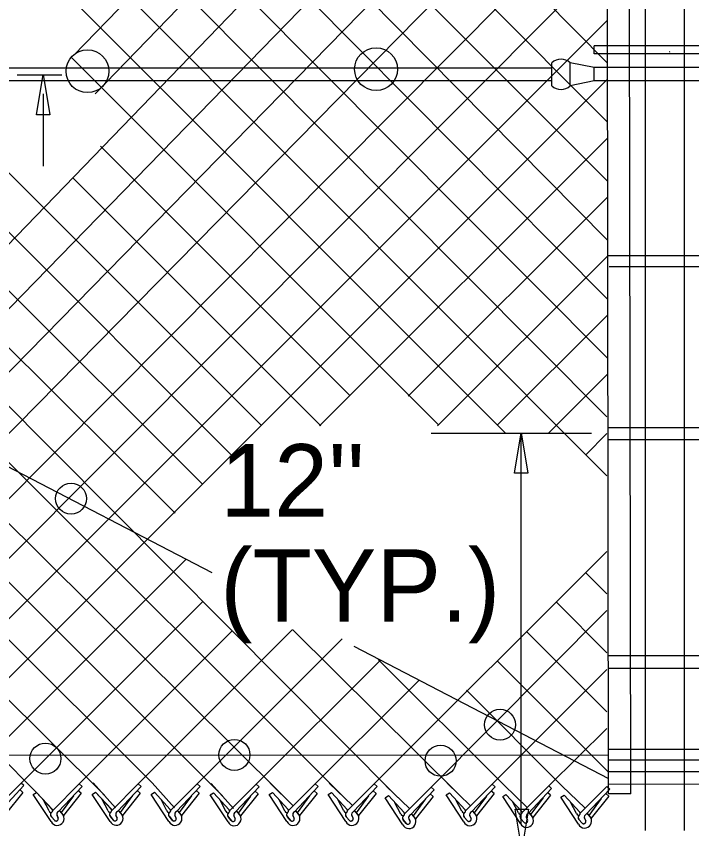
# Model space of a CAD drawing. Extents: x 0 to 1270, y 0 to 830.
# Drawn here: x 1076.4 to 1122.5, y 379.2 to 434.7 of the extents above; entities that cross this region are included whole.
import ezdxf

# ---------------------------------------------------------------- set-up
doc = ezdxf.new("R2010")
doc.units = 0
for name, color, linetype in [('CT_Dimensions', 7, 'Continuous'), ('sb_Chainlink Fence', 7, 'Continuous'), ('sb_Existing Structural Steel', 7, 'Continuous')]:
    doc.layers.add(name, color=color, linetype=linetype)

msp = doc.modelspace()

# ---------------------------------------------------------------- linework, layer by layer
at = {"layer": 'CT_Dimensions'}
for p, q in [((1076.416, 430.664), (1079.472, 430.664)), ((1078.212, 424.432), (1078.212, 429.374)), ((1104.699, 406.174), (1115.654, 406.174)), ((1110.838, 379.484), (1110.838, 406.15))]:
    msp.add_line(p, q, dxfattribs=at)
for points in [[(1077.742, 427.941), (1078.2, 430.69), (1078.658, 427.941)], [(1110.377, 403.447), (1110.835, 406.195), (1111.293, 403.447)], [(1111.347, 380.501), (1110.889, 377.753), (1110.431, 380.501)]]:
    msp.add_lwpolyline(points, close=True, dxfattribs=at)
at = {"layer": 'sb_Chainlink Fence'}
for p, q in [((1044.256, 382.248), (1098.445, 437.888)), ((1048.287, 382.219), (1102.547, 437.615)), ((1052.315, 382.241), (1106.711, 437.544)), ((1056.544, 382.282), (1111.127, 437.209)), ((1060.571, 382.293), (1115.159, 437.067)), ((1039.188, 436.446), (1094.487, 381.494)), ((1040.228, 382.257), (1093.004, 436.872)), ((1080.257, 431.977), (1084.95, 436.832)), ((1081.744, 429.361), (1088.977, 436.843)), ((1099.959, 436.36), (1116.708, 419.39)), ((1031.622, 436.195), (1085.642, 382.286)), ((1035.648, 436.213), (1090.432, 381.402)), ((1043.689, 436.242), (1098.531, 381.514)), ((1047.716, 436.271), (1102.424, 381.3)), ((1051.55, 436.141), (1087.218, 400.727)), ((1055.579, 436.14), (1089.078, 402.691)), ((1059.605, 436.158), (1091.036, 404.701)), ((1063.644, 436.155), (1093.051, 406.762)), ((1079.757, 436.244), (1109.778, 406.178)), ((1083.784, 436.262), (1116.704, 403.272)), ((1087.874, 436.269), (1116.705, 407.302)), ((1091.901, 436.28), (1116.706, 411.331)), ((1095.928, 436.309), (1116.707, 415.361)), ((1104.049, 436.097), (1116.709, 423.42)), ((1108.081, 436.119), (1116.71, 427.449)), ((1112.174, 436.119), (1116.711, 431.479)), ((1027.943, 435.607), (1082.374, 381.44)), ((1064.598, 382.284), (1116.712, 434.383)), ((1026.037, 433.482), (1077.739, 381.642)), ((1080.095, 431.873), (1105.213, 406.719)), ((1068.629, 382.255), (1116.711, 430.352)), ((1082.104, 425.788), (1099.132, 408.756)), ((1097.06, 406.674), (1116.71, 426.32)), ((1080.232, 423.61), (1097.161, 406.686)), ((1103.132, 408.718), (1116.709, 422.289)), ((1105.124, 406.677), (1116.708, 418.257)), ((1109.253, 406.777), (1116.707, 414.226)), ((1112.679, 406.17), (1116.706, 410.194)), ((1100.8, 382.218), (1116.703, 398.1)), ((1072.658, 382.277), (1087.952, 397.568)), ((1076.684, 382.28), (1089.074, 394.665)), ((1113.254, 394.631), (1116.701, 391.184)), ((1104.693, 382.004), (1116.702, 394.068)), ((1080.66, 382.22), (1091.09, 392.647)), ((1084.687, 382.231), (1095.231, 392.766)), ((1095.249, 392.753), (1106.591, 381.491)), ((1111.215, 392.637), (1116.7, 387.154)), ((1087.807, 381.312), (1098.624, 392.122)), ((1092.745, 382.192), (1101.229, 390.68)), ((1101.075, 390.712), (1109.653, 382.147)), ((1109.2, 390.621), (1116.811, 383.031)), ((1108.86, 382.195), (1116.701, 390.037)), ((1095.867, 381.304), (1103.895, 389.329)), ((1107.101, 388.623), (1113.619, 382.099)), ((1112.725, 382.083), (1116.7, 386.005)), ((1074.87, 380.458), (1076.684, 382.28)), ((1075.269, 380.387), (1076.882, 382.1)), ((1076.882, 382.1), (1076.684, 382.28)), ((1078.847, 380.399), (1080.66, 382.22)), ((1079.246, 380.328), (1080.858, 382.041)), ((1080.858, 382.041), (1080.66, 382.22)), ((1081.615, 382.294), (1083.133, 380.585)), ((1082.873, 380.409), (1084.687, 382.231)), ((1083.272, 380.338), (1084.885, 382.051)), ((1084.885, 382.051), (1084.687, 382.231)), ((1085.642, 382.286), (1087.16, 380.577)), ((1086.901, 380.401), (1088.714, 382.222)), ((1087.299, 380.33), (1088.912, 382.043)), ((1088.912, 382.043), (1088.714, 382.222)), ((1089.673, 382.256), (1091.191, 380.547)), ((1090.932, 380.371), (1092.745, 382.192)), ((1091.331, 380.3), (1092.943, 382.013)), ((1092.943, 382.013), (1092.745, 382.192)), ((1093.702, 382.278), (1095.273, 380.71)), ((1094.96, 380.393), (1096.774, 382.215)), ((1095.359, 380.322), (1096.972, 382.035)), ((1096.972, 382.035), (1096.774, 382.215)), ((1097.728, 382.281), (1099.333, 380.746)), ((1098.987, 380.396), (1100.8, 382.218)), ((1099.385, 380.325), (1100.998, 382.038)), ((1100.998, 382.038), (1100.8, 382.218)), ((1101.621, 382.068), (1103.226, 380.533)), ((1102.879, 380.183), (1104.693, 382.004)), ((1104.891, 381.825), (1104.693, 382.004)), ((1105.788, 382.259), (1107.393, 380.724)), ((1107.046, 380.374), (1108.86, 382.195)), ((1107.445, 380.303), (1109.058, 382.016)), ((1109.058, 382.016), (1108.86, 382.195)), ((1109.653, 382.147), (1111.258, 380.612)), ((1110.911, 380.262), (1112.725, 382.083)), ((1112.923, 381.904), (1112.725, 382.083)), ((1113.619, 382.099), (1115.224, 380.564)), ((1114.878, 380.214), (1116.691, 382.035)), ((1116.889, 381.856), (1116.691, 382.035)), ((1076.815, 381.637), (1075.608, 380.12)), ((1076.815, 381.637), (1076.617, 381.817)), ((1077.516, 381.49), (1077.739, 381.642)), ((1078.735, 379.646), (1077.516, 381.49)), ((1077.739, 381.642), (1078.817, 380.481)), ((1077.739, 381.642), (1078.824, 380.474)), ((1080.272, 381.412), (1079.423, 380.257)), ((1080.791, 381.578), (1079.585, 380.061)), ((1080.791, 381.578), (1080.593, 381.757)), ((1081.543, 381.5), (1081.766, 381.653)), ((1082.761, 379.656), (1081.543, 381.5)), ((1081.766, 381.653), (1082.844, 380.491)), ((1081.766, 381.653), (1082.851, 380.484)), ((1084.298, 381.422), (1083.45, 380.267)), ((1084.818, 381.588), (1083.611, 380.071)), ((1084.818, 381.588), (1084.62, 381.768)), ((1085.57, 381.492), (1085.793, 381.644)), ((1086.788, 379.647), (1085.57, 381.492)), ((1085.793, 381.644), (1086.871, 380.482)), ((1085.793, 381.644), (1086.878, 380.476)), ((1088.325, 381.414), (1087.477, 380.259)), ((1088.845, 381.58), (1087.639, 380.063)), ((1088.845, 381.58), (1088.647, 381.759)), ((1089.601, 381.462), (1089.824, 381.615)), ((1090.82, 379.618), (1089.601, 381.462)), ((1089.824, 381.615), (1090.902, 380.453)), ((1089.824, 381.615), (1090.909, 380.446)), ((1092.357, 381.384), (1091.508, 380.229)), ((1092.876, 381.55), (1091.67, 380.033)), ((1092.876, 381.55), (1092.678, 381.729)), ((1093.63, 381.485), (1093.853, 381.637)), ((1094.848, 379.64), (1093.63, 381.485)), ((1093.853, 381.637), (1094.931, 380.475)), ((1093.853, 381.637), (1094.938, 380.468)), ((1096.385, 381.406), (1095.536, 380.251)), ((1096.905, 381.573), (1095.698, 380.055)), ((1096.905, 381.573), (1096.707, 381.752)), ((1097.656, 381.487), (1097.879, 381.64)), ((1098.874, 379.643), (1097.656, 381.487)), ((1097.879, 381.64), (1098.957, 380.478)), ((1097.879, 381.64), (1098.964, 380.471)), ((1100.411, 381.409), (1099.563, 380.254)), ((1100.931, 381.575), (1099.725, 380.058)), ((1100.931, 381.575), (1100.733, 381.755)), ((1101.549, 381.274), (1101.772, 381.426)), ((1101.772, 381.426), (1102.85, 380.264)), ((1101.772, 381.426), (1102.857, 380.258)), ((1103.278, 380.112), (1104.891, 381.825)), ((1104.824, 381.362), (1104.626, 381.541)), ((1105.716, 381.465), (1105.939, 381.617)), ((1106.934, 379.621), (1105.716, 381.465)), ((1105.939, 381.617), (1107.017, 380.456)), ((1105.939, 381.617), (1107.024, 380.449)), ((1108.471, 381.387), (1107.623, 380.232)), ((1108.991, 381.553), (1107.784, 380.036)), ((1108.991, 381.553), (1108.793, 381.732)), ((1109.581, 381.353), (1109.804, 381.505)), ((1109.804, 381.505), (1110.882, 380.343)), ((1109.804, 381.505), (1110.889, 380.336)), ((1111.31, 380.19), (1112.923, 381.904)), ((1112.856, 381.441), (1111.649, 379.923)), ((1112.856, 381.441), (1112.658, 381.62)), ((1113.547, 381.305), (1113.77, 381.457)), ((1113.77, 381.457), (1114.848, 380.295)), ((1113.77, 381.457), (1114.855, 380.289)), ((1115.277, 380.143), (1116.889, 381.856)), ((1116.822, 381.393), (1115.616, 379.876)), ((1116.822, 381.393), (1116.624, 381.572)), ((1078.596, 380.373), (1078.19, 381.149)), ((1082.623, 380.384), (1082.217, 381.159)), ((1086.65, 380.375), (1086.244, 381.151)), ((1090.681, 380.345), (1090.275, 381.121)), ((1094.709, 380.368), (1094.303, 381.144)), ((1098.736, 380.371), (1098.33, 381.146)), ((1102.767, 379.429), (1101.549, 381.274)), ((1102.629, 380.157), (1102.223, 380.933)), ((1104.304, 381.196), (1103.456, 380.041)), ((1104.824, 381.362), (1103.617, 379.844)), ((1106.796, 380.348), (1106.39, 381.124)), ((1110.799, 379.508), (1109.581, 381.353)), ((1110.661, 380.236), (1110.255, 381.012)), ((1112.336, 381.275), (1111.488, 380.12)), ((1114.766, 379.46), (1113.547, 381.305)), ((1114.627, 380.188), (1114.221, 380.964)), ((1116.303, 381.227), (1115.454, 380.072)), ((1079.313, 380.375), (1079.561, 380.082)), ((1079.316, 380.371), (1079.562, 380.081)), ((1083.34, 380.386), (1083.587, 380.093)), ((1083.343, 380.381), (1083.589, 380.092)), ((1087.367, 380.377), (1087.615, 380.084)), ((1087.37, 380.373), (1087.616, 380.083)), ((1091.398, 380.348), (1091.646, 380.054)), ((1091.401, 380.343), (1091.647, 380.053)), ((1095.427, 380.37), (1095.674, 380.077)), ((1095.43, 380.365), (1095.675, 380.076)), ((1099.453, 380.373), (1099.701, 380.08)), ((1099.456, 380.368), (1099.702, 380.079)), ((1107.513, 380.35), (1107.76, 380.057)), ((1107.516, 380.346), (1107.762, 380.056)), ((1078.96, 379.738), (1078.758, 379.98)), ((1078.758, 379.98), (1078.981, 379.716)), ((1079.221, 379.881), (1079.14, 380.058)), ((1079.14, 380.052), (1079.221, 379.885)), ((1079.561, 380.082), (1079.579, 380.048)), ((1079.579, 380.048), (1079.594, 380.012)), ((1082.987, 379.748), (1082.785, 379.99)), ((1082.785, 379.99), (1083.008, 379.727)), ((1083.248, 379.891), (1083.166, 380.068)), ((1083.167, 380.062), (1083.248, 379.895)), ((1083.587, 380.093), (1083.606, 380.059)), ((1083.606, 380.059), (1083.621, 380.022)), ((1087.014, 379.74), (1086.812, 379.982)), ((1086.812, 379.982), (1087.035, 379.718)), ((1087.275, 379.883), (1087.194, 380.06)), ((1087.194, 380.054), (1087.275, 379.887)), ((1087.615, 380.084), (1087.633, 380.05)), ((1087.633, 380.05), (1087.648, 380.014)), ((1091.045, 379.71), (1090.843, 379.952)), ((1090.843, 379.952), (1091.066, 379.689)), ((1091.306, 379.853), (1091.225, 380.03)), ((1091.225, 380.024), (1091.306, 379.857)), ((1091.646, 380.054), (1091.664, 380.02)), ((1091.664, 380.02), (1091.68, 379.984)), ((1095.074, 379.733), (1094.872, 379.974)), ((1094.872, 379.974), (1095.094, 379.711)), ((1095.335, 379.875), (1095.253, 380.052)), ((1095.253, 380.046), (1095.335, 379.879)), ((1095.674, 380.077), (1095.692, 380.043)), ((1095.692, 380.043), (1095.708, 380.006)), ((1099.1, 379.735), (1098.898, 379.977)), ((1098.898, 379.977), (1099.121, 379.714)), ((1099.361, 379.878), (1099.28, 380.055)), ((1099.28, 380.049), (1099.361, 379.882)), ((1099.701, 380.08), (1099.719, 380.046)), ((1099.719, 380.046), (1099.734, 380.009)), ((1102.993, 379.522), (1102.791, 379.764)), ((1102.791, 379.764), (1103.014, 379.5)), ((1103.254, 379.665), (1103.172, 379.842)), ((1103.173, 379.836), (1103.254, 379.669)), ((1103.346, 380.159), (1103.594, 379.866)), ((1103.349, 380.155), (1103.595, 379.865)), ((1103.594, 379.866), (1103.612, 379.832)), ((1103.612, 379.832), (1103.627, 379.796)), ((1107.16, 379.713), (1106.958, 379.955)), ((1106.958, 379.955), (1107.181, 379.691)), ((1107.421, 379.856), (1107.339, 380.033)), ((1107.34, 380.027), (1107.421, 379.86)), ((1107.76, 380.057), (1107.779, 380.023)), ((1107.779, 380.023), (1107.794, 379.987)), ((1111.025, 379.601), (1110.823, 379.843)), ((1110.823, 379.843), (1111.046, 379.579)), ((1111.286, 379.744), (1111.204, 379.921)), ((1111.205, 379.914), (1111.286, 379.748)), ((1111.378, 380.238), (1111.625, 379.945)), ((1111.381, 380.234), (1111.627, 379.944)), ((1111.625, 379.945), (1111.644, 379.911)), ((1111.644, 379.911), (1111.659, 379.875)), ((1114.991, 379.553), (1114.789, 379.795)), ((1114.789, 379.795), (1115.012, 379.531)), ((1115.252, 379.696), (1115.171, 379.873)), ((1115.171, 379.867), (1115.252, 379.7)), ((1115.344, 380.19), (1115.592, 379.897)), ((1115.347, 380.186), (1115.593, 379.896)), ((1115.592, 379.897), (1115.61, 379.863)), ((1115.61, 379.863), (1115.625, 379.827))]:
    msp.add_line(p, q, dxfattribs=at)
for centre, radius, start, end in [((1078.722, 380.395), 0.128, 189.9304, 40.9785), ((1078.888, 380.122), 0.192, 126.9947, 219.7983), ((1078.893, 380.121), 0.195, 127.7656, 226.3328), ((1079.333, 380.138), 0.209, 114.8422, 203.5167), ((1082.749, 380.406), 0.128, 189.9304, 40.9785), ((1082.915, 380.132), 0.192, 126.9947, 219.7983), ((1082.92, 380.132), 0.195, 127.7656, 226.3328), ((1083.36, 380.148), 0.209, 114.8422, 203.5167), ((1086.776, 380.397), 0.128, 189.9304, 40.9785), ((1086.942, 380.124), 0.192, 126.9947, 219.7983), ((1086.947, 380.123), 0.195, 127.7656, 226.3328), ((1087.387, 380.14), 0.209, 114.8422, 203.5167), ((1090.807, 380.368), 0.128, 189.9304, 40.9785), ((1091.419, 380.11), 0.209, 114.8422, 203.5167), ((1094.835, 380.39), 0.128, 189.9304, 40.9785), ((1095.002, 380.116), 0.192, 126.9947, 219.7983), ((1095.007, 380.116), 0.195, 127.7656, 226.3328), ((1095.447, 380.132), 0.209, 114.8422, 203.5167), ((1098.862, 380.393), 0.128, 189.9304, 40.9785), ((1099.028, 380.119), 0.192, 126.9947, 219.7983), ((1099.033, 380.119), 0.195, 127.7656, 226.3328), ((1099.473, 380.135), 0.209, 114.8422, 203.5167), ((1102.755, 380.179), 0.128, 189.9304, 40.9785), ((1106.922, 380.37), 0.128, 189.9304, 40.9785), ((1107.533, 380.113), 0.209, 114.8422, 203.5167), ((1110.787, 380.258), 0.128, 189.9304, 40.9785), ((1114.753, 380.21), 0.128, 189.9304, 40.9785), ((1079.154, 379.853), 0.468, 206.3202, 29.2269), ((1079.077, 379.835), 0.152, 219.8632, 17.4852), ((1079.077, 379.835), 0.152, 230.7826, 19.2656), ((1083.181, 379.863), 0.468, 206.3202, 29.2269), ((1083.103, 379.845), 0.152, 219.8632, 17.4852), ((1083.104, 379.845), 0.152, 230.7826, 19.2656), ((1087.208, 379.855), 0.468, 206.3202, 29.2269), ((1087.131, 379.837), 0.152, 219.8632, 17.4852), ((1087.131, 379.836), 0.152, 230.7826, 19.2656), ((1090.973, 380.094), 0.192, 126.9947, 219.7983), ((1090.978, 380.093), 0.195, 127.7656, 226.3328), ((1091.239, 379.825), 0.468, 206.3202, 29.2269), ((1091.162, 379.807), 0.152, 219.8632, 17.4852), ((1091.162, 379.807), 0.152, 230.7826, 19.2656), ((1095.267, 379.847), 0.468, 206.3202, 29.2269), ((1095.19, 379.83), 0.152, 219.8632, 17.4852), ((1095.191, 379.829), 0.152, 230.7826, 19.2656), ((1099.294, 379.85), 0.468, 206.3202, 29.2269), ((1099.217, 379.833), 0.152, 219.8632, 17.4852), ((1099.217, 379.832), 0.152, 230.7826, 19.2656), ((1102.921, 379.905), 0.192, 126.9947, 219.7983), ((1102.926, 379.905), 0.195, 127.7656, 226.3328), ((1103.187, 379.637), 0.468, 206.3202, 29.2269), ((1103.366, 379.921), 0.209, 114.8422, 203.5167), ((1107.088, 380.097), 0.192, 126.9947, 219.7983), ((1107.093, 380.096), 0.195, 127.7656, 226.3328), ((1107.354, 379.828), 0.468, 206.3202, 29.2269), ((1107.276, 379.81), 0.152, 219.8632, 17.4852), ((1107.277, 379.81), 0.152, 230.7826, 19.2656), ((1110.953, 379.984), 0.192, 126.9947, 219.7983), ((1110.958, 379.984), 0.195, 127.7656, 226.3328), ((1111.219, 379.716), 0.468, 206.3202, 29.2269), ((1111.142, 379.698), 0.152, 219.8632, 17.4852), ((1111.142, 379.697), 0.152, 230.7826, 19.2656), ((1111.398, 380), 0.209, 114.8422, 203.5167), ((1114.919, 379.936), 0.192, 126.9947, 219.7983), ((1114.924, 379.936), 0.195, 127.7656, 226.3328), ((1115.185, 379.668), 0.468, 206.3202, 29.2269), ((1115.108, 379.649), 0.152, 230.7826, 19.2656), ((1115.365, 379.953), 0.209, 114.8422, 203.5167), ((1103.11, 379.619), 0.152, 219.8632, 17.4852), ((1103.11, 379.618), 0.152, 230.7826, 19.2656), ((1115.108, 379.65), 0.152, 219.8632, 17.4852)]:
    msp.add_arc(centre, radius, start, end, dxfattribs=at)
at = {"layer": 'sb_Existing Structural Steel'}
for p, q in [((1119.329, 379.043), (1119.329, 442.988)), ((1122.001, 379.034), (1122.001, 442.988)), ((1116.816, 381.55), (1116.728, 439.036)), ((1118.324, 381.55), (1118.236, 439.036)), ((1125.314, 432.644), (1115.823, 432.644)), ((1115.823, 432.088), (1115.823, 432.644)), ((1125.314, 432.088), (1115.823, 432.088)), ((1120.985, 432.233), (1121.021, 432.269)), ((1112.947, 429.915), (1112.947, 431.492)), ((1115.823, 431.165), (1114.185, 431.492)), ((1114.185, 429.915), (1114.185, 431.492)), ((1030.462, 431.15), (1112.934, 431.144)), ((1124.96, 431.165), (1115.823, 431.165)), ((1115.823, 430.243), (1115.823, 431.165)), ((1030.466, 430.285), (1112.971, 430.274)), ((1115.823, 430.243), (1114.185, 429.915)), ((1124.953, 430.243), (1115.823, 430.243)), ((1124.47, 418.306), (1116.795, 418.306)), ((1124.494, 417.557), (1116.85, 417.557)), ((1124.501, 406.544), (1116.805, 406.544)), ((1115.254, 404.711), (1116.705, 406.163)), ((1124.531, 405.737), (1116.833, 405.737)), ((1074.126, 404.767), (1089.725, 396.664)), ((1115.27, 396.648), (1116.702, 395.213)), ((1099.403, 391.637), (1116.806, 382.597)), ((1124.533, 390.961), (1116.804, 390.961)), ((1124.533, 390.114), (1116.826, 390.114)), ((440.979, 383.869), (1116.811, 384.201)), ((1124.525, 384.561), (1116.81, 384.573)), ((1124.535, 383.837), (1116.815, 383.842)), ((1124.523, 383.04), (1116.813, 383.037)), ((1124.555, 382.211), (1116.826, 382.168)), ((1118.324, 381.55), (1116.816, 381.55))]:
    msp.add_line(p, q, dxfattribs=at)
for centre, radius in [((1100.93, 431.049), 1.465), ((1081.221, 430.911), 1.465), ((1080.096, 401.708), 1.06), ((1109.399, 386.265), 1.06), ((1091.258, 384.198), 1.06), ((1078.348, 383.951), 1.06), ((1105.338, 383.798), 1.06)]:
    msp.add_circle(centre, radius, dxfattribs=at)
for centre, start, end in [((1113.566, 430.837), 46.6143, 133.3857), ((1113.566, 430.57), 226.6143, 313.3857)]:
    msp.add_arc(centre, 0.901, start, end, dxfattribs=at)

# ---------------------------------------------------------------- texts
at = {"layer": 'CT_Dimensions'}
for s, p in [("12'' ", (1090.292, 400.481)), ('(TYP.)', (1090.292, 393.303))]:
    msp.add_text(s, height=4.95, rotation=360, dxfattribs=at).set_placement(p)

doc.saveas('drawing.dxf')
